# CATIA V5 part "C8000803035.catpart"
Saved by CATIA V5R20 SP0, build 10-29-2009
Part number: C8000803035
Source: Unknown
Property "A": "50"
Property "ARTICLENO": "C8000803035"
Property "B": "23"
Property "BOMINFO": "C8000803035"
Property "C": "95"
Property "CA": "C8000803035"
Property "D1": "85"
Property "DES": "ROTATING EYEBOLT WITH RING Ton 8 M30x35"
Property "E": "95"
Property "H": "205"
Property "L": "35"
Property "LINA": "C8000803035"
Property "NB": "C8000803035"
Property "NBSYN": "$CODE."
Property "NN": "C800"
Property "NT": "Rotating eyebolt with ring"
Property "SIZE": "M30"
Property "SUPPLIER": "CF"
Property "SW": "75"
Property "WEIGHT": "5300"
Property "WLL": "8.00"
Bounding box of the stored display mesh (mm): x -47.825 to 48, y -35 to 227.825, z -42.5 to 42.5
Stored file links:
  C:\Users\Utente\Desktop\3D files 800\C8000803035.catpart
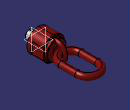
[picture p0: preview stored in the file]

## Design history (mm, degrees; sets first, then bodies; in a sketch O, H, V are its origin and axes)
Body1 "Geometry.1" (main body)
  Solid1 "C8000803035.catpart": solid without history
